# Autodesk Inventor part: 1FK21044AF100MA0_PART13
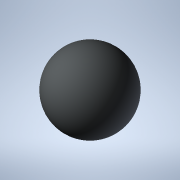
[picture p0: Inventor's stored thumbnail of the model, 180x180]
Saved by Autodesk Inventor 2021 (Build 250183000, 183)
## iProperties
Created: 2025-04
Part Number: 1FK21044AF100MA0_PART13
Material: Generic
Catalog Web Link: www.3dfindit.com
Description: -Servo synchronous motor
Document SubType Name: Modeling
Designer: psAdmin
Mass: 0.137258 g
Surface Area: 1.2868 cm^2
Volume: 0.137258 cm^3
Density: 1 g/cm^3
Appearance: PSOLRGB-212-217-219
Category: PARTsolutions
Title: 1FK21044AF100MA0_PART13
Author: Cadenas PARTsolutions
Comments: Servo synchronous motor
Sending System: PARTsolutions
Preprocessor: ST-DEVELOPER v19.3
PSOL_IDENT_0: {$CADENAS_DATA/23d-libs/siemens_ag/_cat_/ec/e4/1fk21044af100ma0.prj},216 {VTYP=3D},{NB=1FK21044AF100
PSOL_IDENT_1: MA0_PART13},{LINA=1FK21044AF100MA0_PART13},{NN=1FK21044AF100MA0_PART13},{NOPRJ=TRUE},{DATE=19.08.202
PSOL_IDENT_2: 5 14:01:05},{GEOMDATE=30.07.2025 02:01:01},{VERSION=},{LINEID=10},{WBVAR=},{WBNUMERIC=}  {NB=1FK2104
PSOL_IDENT_3: 4AF100MA0_PART13},{LINA=1FK21044AF100MA0_PART13},{KT=DUMMY},{PREVIEW=../../../_pool_/cb/72/p_d211_xx
PSOL_IDENT_4: _00434j.png},{DESCSHORT=SIMOTICS S-1FK2 HD, SINAMICS S210 3AC 400V-480V, 1.27 Nm, 3000 rpm},{DESCLON
PSOL_IDENT_5: G=SIMOTICS S-1FK2 HD servo motor M0=1.27 Nm; PN = 0.4 kW at nN=3000 rpm (380-480 V); PN = 0.2 kW at
PSOL_IDENT_6: nN=1500 rpm (200-240 V); with holding brake; degree of protection IP64; cylindrical shaft D19x40mm;
PSOL_IDENT_7: absolute encoder 22-bit + 12-bit multiturn (encoder AM22DQC); with OCC interface; plug size M17, rot
PSOL_IDENT_8: atable; SIMOTICS S-1FK2 servomotorfor a wide range of uses in industrial environments. SIMOTICS S‑1F
PSOL_IDENT_9: K2 servomotors are compact synchronous motors with a high dynamic performance that set themselves ap
PSOL_IDENT_10: art as a result of their high power density, degree of protection and overload capability. The motor
PSOL_IDENT_11: s are available in two variants: as High Dynamic variant (highest dynamic performance as a result of
PSOL_IDENT_12: the low intrinsic moment of inertia for applications demanding a high dynamic performance with low
PSOL_IDENT_13: moved masses) - and as Compact variant (precise and stable closed-loop control for medium up to larg
PSOL_IDENT_14: e moved masses as a result of a medium intrinsic moment of inertia). SIMOTICSS‑1FK2 servomotors full
PSOL_IDENT_15: y exploit their strengths in a system with the SINAMICSS210 frequency converter and simple connectio
PSOL_IDENT_16: n using the one cable connection (OCC). Advantages include the short control and positioning times,
PSOL_IDENT_17: fast and precise correction of disturbing quantities as well as stable control with a high dynamic p
PSOL_IDENT_18: erformance. The servo motors can be configured to address a wide range of requirements. For example
PSOL_IDENT_19: with and without holding brake, IP64 or IP65 degree of protection, singleturn or multiturn absolute
PSOL_IDENT_20: encoders - to name just a few. Further, the servomotors are available in different shaft heights ext
PSOL_IDENT_21: ending from 20 to 100. A shaft sealing ring is available to achieve an IP65 degree of protection and
PSOL_IDENT_22: for subsequent mounting at the motor or as spare part. SIMOTICS - the optimum motor for each and ev
PSOL_IDENT_23: ery motion control application.},{INTNO=195125043275},{SUPPLIERALTNO=1FK2104-4AF10-0MA0},{MANUID=1FK
PSOL_IDENT_24: 21044AF100MA0},{MANUNAME=Siemens},{MANUTYPEDESC=Synchronous motor 1FK2-HD 1.27 NM},{AAU732=SIMOTICS}
PSOL_IDENT_25: ,{AAO057=S-1FK2},{AAU734=SIMOTICS S-1FK2 HD servo motor M0=1.27 Nm; PN = 0.4 kW at nN=3000 rpm (380-
PSOL_IDENT_26: 480 V); PN = 0.2 kW at nN=1500 rpm (200-240 V); with holding brake; degree of protection IP64; cylin
PSOL_IDENT_27: drical shaft D19x40mm; absolute encoder 22-bit + 12-bit multiturn (encoder AM22DQC); with OCC interf
PSOL_IDENT_28: ace; plug size M17, rotatable;},{AAW338=Synchronous motor 1FK2-HD 1.27 NM},{AAO742=SIMOTICS},{AAO663=
PSOL_IDENT_29: 4042948694015},{NOCUPEROU=1},{PRICEQUANTITY=1},{QUANTITYMIN=1},{QUANTITYINT=1},{CTN=85015100},{COO=D
PSOL_IDENT_30: E},{AAO676=1FK2104-4AF10-0MA0},{AAO677=Siemens AG},{ORDERUNIT=C62},{CONTENTUNIT=C62}
NB: 1FK21044AF100MA0_PART13
NT: Servo synchronous motor
NBSYN: $MANUID._PART13
LINA: 1FK21044AF100MA0_PART13
CATALOG: SIEMENS
PREVIEW: ../../../_pool_/cb/72/p_d211_xx_00434j.png
DESCSHORT: SIMOTICS S-1FK2 HD, SINAMICS S210 3AC 400V-480V, 1.27 Nm, 3000 rpm
DESCLONG: SIMOTICS S-1FK2 HD servo motor M0=1.27 Nm; PN = 0.4 kW at nN=3000 rpm (380-480 V); PN = 0.2 kW at nN=1500 rpm (200-240 V); with holding brake; degree of protect
INTNO: 195125043275
SUPPLIERALTNO: 1FK2104-4AF10-0MA0
MANUID: 1FK21044AF100MA0
MANUNAME: Siemens
MANUTYPEDESC: Synchronous motor 1FK2-HD 1.27 NM
AAU732: SIMOTICS
AAO057: S-1FK2
AAU734: SIMOTICS S-1FK2 HD servo motor M0=1.27 Nm; PN = 0.4 kW at nN=3000 rpm (380-480 V); PN = 0.2 kW at nN=1500 rpm (200-240 V); with holding brake; degree of protect
AAW338: Synchronous motor 1FK2-HD 1.27 NM
AAO742: SIMOTICS
AAO663: 4042948694015.0
NOCUPEROU: 1
PRICEQUANTITY: 1
QUANTITYMIN: 1
QUANTITYINT: 1
CTN: 85015100
COO: DE
ARTICLENO: 1FK21044AF100MA0_PART13
BOMINFO: 1FK21044AF100MA0_PART13
CREATOR: CADENAS GmbH
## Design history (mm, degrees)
feature "2025_04_17_15_33_01_0673"
body "Solid1"
